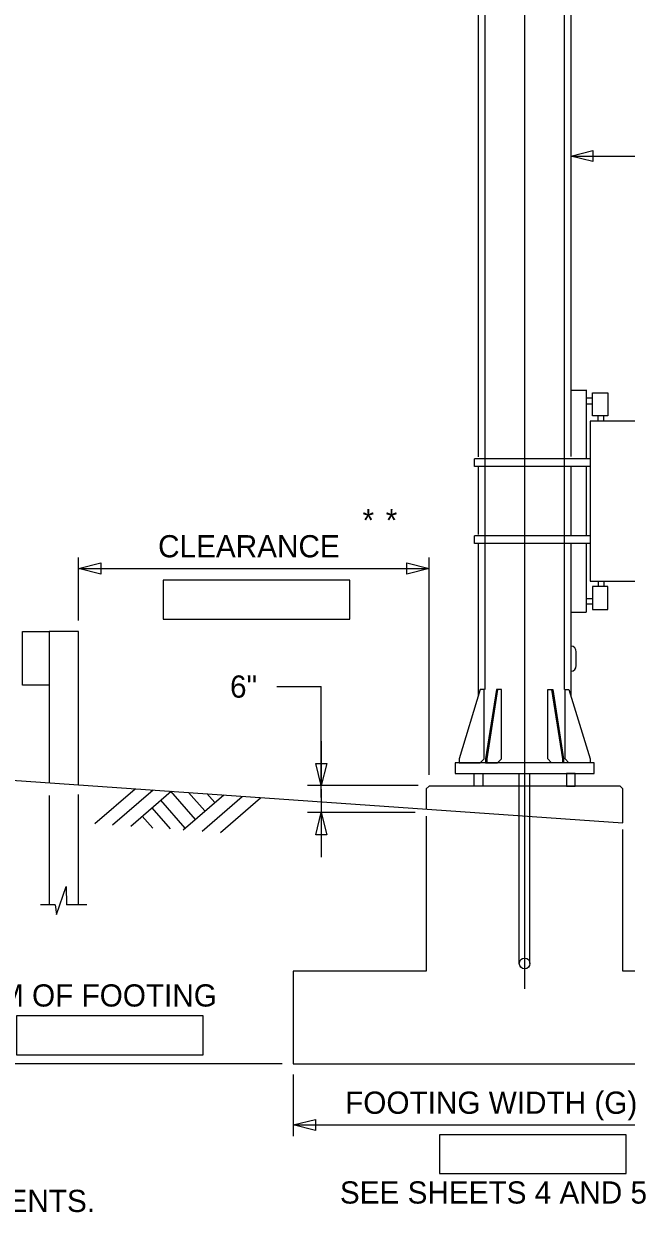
# Model space of a CAD drawing. Extents: x 3829340 to 3831660, y 499389 to 501171.
# Drawn here: x 3829492.7 to 3829574, y 499644 to 499805.2 of the extents above; entities that cross this region are included whole.
import ezdxf

# ---------------------------------------------------------------- set-up
doc = ezdxf.new("R2010")
doc.units = 0
for name, color, linetype in [('0-ANCHOR', 7, 'Continuous'), ('0-DEVICE ATTACH', 7, 'Continuous'), ('CNTR', 7, 'Continuous'), ('Default', 7, 'Continuous'), ('DIM TXT', 7, 'Continuous'), ('foundation', 7, 'Continuous'), ('grade', 7, 'Continuous'), ('structure', 7, 'Continuous')]:
    doc.layers.add(name, color=color, linetype=linetype)

msp = doc.modelspace()

# ---------------------------------------------------------------- linework, layer by layer
at = {"layer": '0-ANCHOR'}
for points in [[(3829553.44, 499704.03), (3829554.61, 499704.03), (3829554.61, 499702.33), (3829553.44, 499702.33)], [(3829567.11, 499704.03), (3829565.94, 499704.03), (3829565.94, 499702.33), (3829567.11, 499702.33)]]:
    msp.add_lwpolyline(points, close=True, dxfattribs=at)
at = {"layer": '0-DEVICE ATTACH'}
for p, q in [((3829553.5, 499745.47), (3829553.51, 499746.51)), ((3829569.11, 499745.47), (3829553.5, 499745.47)), ((3829569.11, 499746.51), (3829553.51, 499746.51)), ((3829553.5, 499735.05), (3829553.51, 499736.1)), ((3829569.11, 499736.1), (3829553.51, 499736.1)), ((3829569.11, 499735.05), (3829553.5, 499735.05))]:
    msp.add_line(p, q, dxfattribs=at)
msp.add_lwpolyline([(3829569.11, 499729.98), (3829575.88, 499729.98), (3829575.88, 499751.59), (3829569.11, 499751.59)], close=True, dxfattribs=at)
msp.add_lwpolyline([(3829569.11, 499729.98), (3829575.88, 499729.98), (3829575.88, 499751.59), (3829569.11, 499751.59)], close=True, dxfattribs=at)
msp.add_lwpolyline([(3829569.11, 499729.98), (3829575.88, 499729.98), (3829575.88, 499751.59), (3829569.11, 499751.59)], close=True, dxfattribs=at)
at = {"layer": 'CNTR'}
msp.add_line((3829560.27, 499935.08), (3829560.27, 499674.93), dxfattribs=at)
at = {"layer": 'Default'}
for p, q in [((3829556.63, 499715.35), (3829555.18, 499705.98)), ((3829563.92, 499715.35), (3829565.37, 499705.98)), ((3829555.18, 499705.98), (3829555.18, 499705.46)), ((3829565.37, 499705.98), (3829565.37, 499705.46))]:
    msp.add_line(p, q, dxfattribs=at)
at = {"layer": 'DIM TXT'}
for p, q in [((3829566.5, 499787.38), (3829578.99, 499787.37)), ((3829500.05, 499724.68), (3829500.05, 499733.2)), ((3829547.38, 499703.83), (3829547.38, 499733.2)), ((3829500.05, 499731.7), (3829547.38, 499731.7)), ((3829526.82, 499715.76), (3829532.82, 499715.76)), ((3829532.82, 499700.79), (3829532.82, 499715.76)), ((3829532.82, 499708.38), (3829532.82, 499702.38)), ((3829545.88, 499702.38), (3829530.97, 499702.38)), ((3829532.82, 499701.91), (3829532.82, 499698.74)), ((3829545.49, 499698.74), (3829530.97, 499698.74)), ((3829532.82, 499698.74), (3829532.82, 499692.74)), ((3829476.2, 499664.88), (3829527.52, 499664.88)), ((3829529.02, 499663.38), (3829529.02, 499655.08)), ((3829529.02, 499656.58), (3829591.52, 499656.58))]:
    msp.add_line(p, q, dxfattribs=at)
for points in [[(3829569.5, 499786.63), (3829566.5, 499787.38), (3829569.5, 499788.13)], [(3829503.05, 499730.95), (3829500.05, 499731.7), (3829503.05, 499732.45)], [(3829544.38, 499732.45), (3829547.38, 499731.7), (3829544.38, 499730.95)], [(3829511.48, 499724.86), (3829536.67, 499724.85), (3829536.67, 499730.1), (3829511.48, 499730.1)], [(3829533.57, 499705.38), (3829532.82, 499702.38), (3829532.07, 499705.38)], [(3829532.07, 499695.74), (3829532.82, 499698.74), (3829533.57, 499695.74)], [(3829491.67, 499666.04), (3829516.86, 499666.04), (3829516.86, 499671.29), (3829491.67, 499671.29)], [(3829532.02, 499655.83), (3829529.02, 499656.58), (3829532.02, 499657.33)], [(3829548.78, 499650.01), (3829573.97, 499650.01), (3829573.97, 499655.26), (3829548.78, 499655.26)]]:
    msp.add_lwpolyline(points, close=True, dxfattribs=at)
at = {"layer": 'foundation'}
for p, q in [((3829559.55, 499678.38), (3829559.55, 499704.03)), ((3829560.99, 499678.38), (3829560.99, 499704.03)), ((3829546.99, 499698.24), (3829546.99, 499677.33)), ((3829573.55, 499677.33), (3829573.55, 499696.46))]:
    msp.add_line(p, q, dxfattribs=at)
for points in [[(3829573.55, 499697.34), (3829573.55, 499701.94), (3829573.16, 499702.33), (3829547.38, 499702.33), (3829546.99, 499701.94), (3829546.99, 499699.21)], [(3829546.99, 499677.33), (3829529.02, 499677.33), (3829529.02, 499664.83), (3829591.52, 499664.83), (3829591.52, 499677.33), (3829573.55, 499677.33)]]:
    msp.add_lwpolyline(points, dxfattribs=at)
msp.add_circle((3829560.27, 499678.38), 0.721, dxfattribs=at)
at = {"layer": 'grade'}
for p, q in [((3829500.05, 499723.18), (3829496.1, 499723.18)), ((3829496.1, 499723.18), (3829496.1, 499702.78)), ((3829500.05, 499702.5), (3829500.05, 499723.18)), ((3829439.08, 499706.78), (3829573.55, 499697.34)), ((3829502.27, 499697.26), (3829507.71, 499701.97)), ((3829504.64, 499697.09), (3829510.11, 499701.82)), ((3829507.1, 499696.91), (3829512.56, 499701.64)), ((3829512.45, 499701.65), (3829515.79, 499697.79)), ((3829514.91, 499701.47), (3829517.08, 499698.96)), ((3829496.1, 499701.05), (3829496.1, 499686.31)), ((3829500.05, 499686.31), (3829500.05, 499701.18)), ((3829511.13, 499700.4), (3829514.39, 499696.63)), ((3829514.16, 499696.4), (3829519.65, 499701.16)), ((3829516.75, 499696.22), (3829522.15, 499700.9)), ((3829517.39, 499701.3), (3829518.43, 499700.1)), ((3829519.2, 499696.04), (3829524.61, 499700.72)), ((3829508.65, 499698.25), (3829510.06, 499696.62)), ((3829509.96, 499699.39), (3829512.44, 499696.53)), ((3829497.09, 499684.98), (3829498.39, 499688.76)), ((3829498.39, 499688.76), (3829498.43, 499686.31)), ((3829496.88, 499686.31), (3829494.91, 499686.31)), ((3829496.88, 499686.31), (3829497.09, 499684.98)), ((3829501.15, 499686.31), (3829498.43, 499686.31))]:
    msp.add_line(p, q, dxfattribs=at)
msp.add_lwpolyline([(3829496.1, 499723.18), (3829496.1, 499715.93), (3829492.47, 499715.93), (3829492.47, 499723.18)], close=True, dxfattribs=at)
at = {"layer": 'structure'}
for p, q in [((3829554.92, 499880.19), (3829554.92, 499715.35)), ((3829565.62, 499880.19), (3829565.62, 499715.35)), ((3829566.52, 499880.19), (3829566.52, 499746.82)), ((3829554.02, 499855.45), (3829554.02, 499746.78)), ((3829566.51, 499755.78), (3829568.57, 499755.78)), ((3829568.57, 499755.8), (3829568.57, 499746.61)), ((3829569.44, 499754.7), (3829568.57, 499754.7)), ((3829568.57, 499753.92), (3829569.44, 499753.92)), ((3829570.18, 499751.59), (3829570.18, 499752.29)), ((3829570.96, 499751.59), (3829570.96, 499752.29)), ((3829554.02, 499745.36), (3829554.02, 499736.28)), ((3829566.52, 499745.4), (3829566.52, 499736.1)), ((3829568.57, 499745.47), (3829568.57, 499736.24)), ((3829554.02, 499734.99), (3829554.02, 499714.5)), ((3829566.52, 499734.99), (3829566.52, 499714.5)), ((3829568.57, 499734.99), (3829568.57, 499725.78)), ((3829570.18, 499729.98), (3829570.18, 499729.28)), ((3829570.96, 499729.98), (3829570.96, 499729.28)), ((3829568.57, 499727.64), (3829569.44, 499727.64)), ((3829566.52, 499725.78), (3829568.57, 499725.78)), ((3829569.44, 499726.86), (3829568.57, 499726.86)), ((3829566.57, 499721.21), (3829566.52, 499721.21)), ((3829567.24, 499718.61), (3829567.24, 499720.43)), ((3829566.52, 499717.83), (3829566.57, 499717.83)), ((3829554.28, 499715.35), (3829551.42, 499705.98)), ((3829554.81, 499705.98), (3829554.81, 499715.35)), ((3829556.46, 499715.35), (3829555.01, 499705.98)), ((3829556.63, 499715.35), (3829556.46, 499715.35)), ((3829557.15, 499715.35), (3829556.63, 499715.35)), ((3829557.15, 499705.98), (3829557.15, 499715.35)), ((3829563.4, 499705.98), (3829563.4, 499715.35)), ((3829563.4, 499715.35), (3829563.92, 499715.35)), ((3829563.92, 499715.35), (3829564.09, 499715.35)), ((3829564.09, 499715.35), (3829565.54, 499705.98)), ((3829565.74, 499705.98), (3829565.74, 499715.35)), ((3829566.26, 499715.35), (3829569.13, 499705.98)), ((3829551.42, 499705.46), (3829554.29, 499705.46)), ((3829554.28, 499705.45), (3829554.81, 499705.98)), ((3829555.01, 499705.98), (3829555.01, 499705.46)), ((3829555.01, 499705.46), (3829556.63, 499705.46)), ((3829556.63, 499705.46), (3829557.15, 499705.98)), ((3829563.91, 499705.46), (3829563.4, 499705.98)), ((3829565.54, 499705.46), (3829563.91, 499705.46)), ((3829565.54, 499705.98), (3829565.54, 499705.46)), ((3829566.26, 499705.45), (3829565.74, 499705.98)), ((3829569.13, 499705.46), (3829566.26, 499705.46))]:
    msp.add_line(p, q, dxfattribs=at)
for points in [[(3829569.44, 499755.41), (3829571.52, 499755.41), (3829571.52, 499752.29), (3829569.44, 499752.29)], [(3829569.44, 499726.15), (3829571.52, 499726.15), (3829571.52, 499729.28), (3829569.44, 499729.28)], [(3829550.9, 499704.03), (3829569.65, 499704.03), (3829569.65, 499705.46), (3829550.9, 499705.46)]]:
    msp.add_lwpolyline(points, close=True, dxfattribs=at)
for points in [[(3829554.81, 499715.35), (3829554.28, 499715.35)], [(3829565.74, 499715.35), (3829566.26, 499715.35)], [(3829551.42, 499705.98), (3829551.42, 499705.46)], [(3829569.13, 499705.98), (3829569.13, 499705.46)]]:
    msp.add_lwpolyline(points, dxfattribs=at)
for centre, start_param, end_param in [((3829566.57, 499720.43), 4.712389, 6.283185), ((3829566.57, 499718.61), 3.141593, 4.712389)]:
    msp.add_ellipse(centre, major_axis=(0, 0.781), ratio=0.866025, start_param=start_param, end_param=end_param, dxfattribs=at)

# ---------------------------------------------------------------- texts
at = {"layer": 'DIM TXT'}
for s, height, p in [('*', 3, (3829538.39, 499736.71)), ('*', 3, (3829541.52, 499736.71)), ('CLEARANCE', 3, (3829510.79, 499733.2)), ('6"', 3, (3829520.5, 499714.26)), ('BOTTOM OF FOOTING', 2.9999, (3829475.5, 499672.56)), ('FOOTING WIDTH (G)', 2.9999, (3829536.04, 499658.08)), ('SEE SHEETS 4 AND 5', 2.9999, (3829535.33, 499645.96)), ('SEE BC-741M FOR CLEARANCE REQUIREMENTS.', 2.9999, (3829406.43, 499644.82))]:
    msp.add_text(s, height=height, dxfattribs=at).set_placement(p)

doc.saveas('drawing.dxf')
